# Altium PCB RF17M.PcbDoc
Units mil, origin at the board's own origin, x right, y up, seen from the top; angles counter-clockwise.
Board outline 1070 x 780 mil, 4 copper layers (Top Layer, MidLayer1, MidLayer2, Bottom Layer); 49 components, 57 nets, 260 pads, 101 vias.
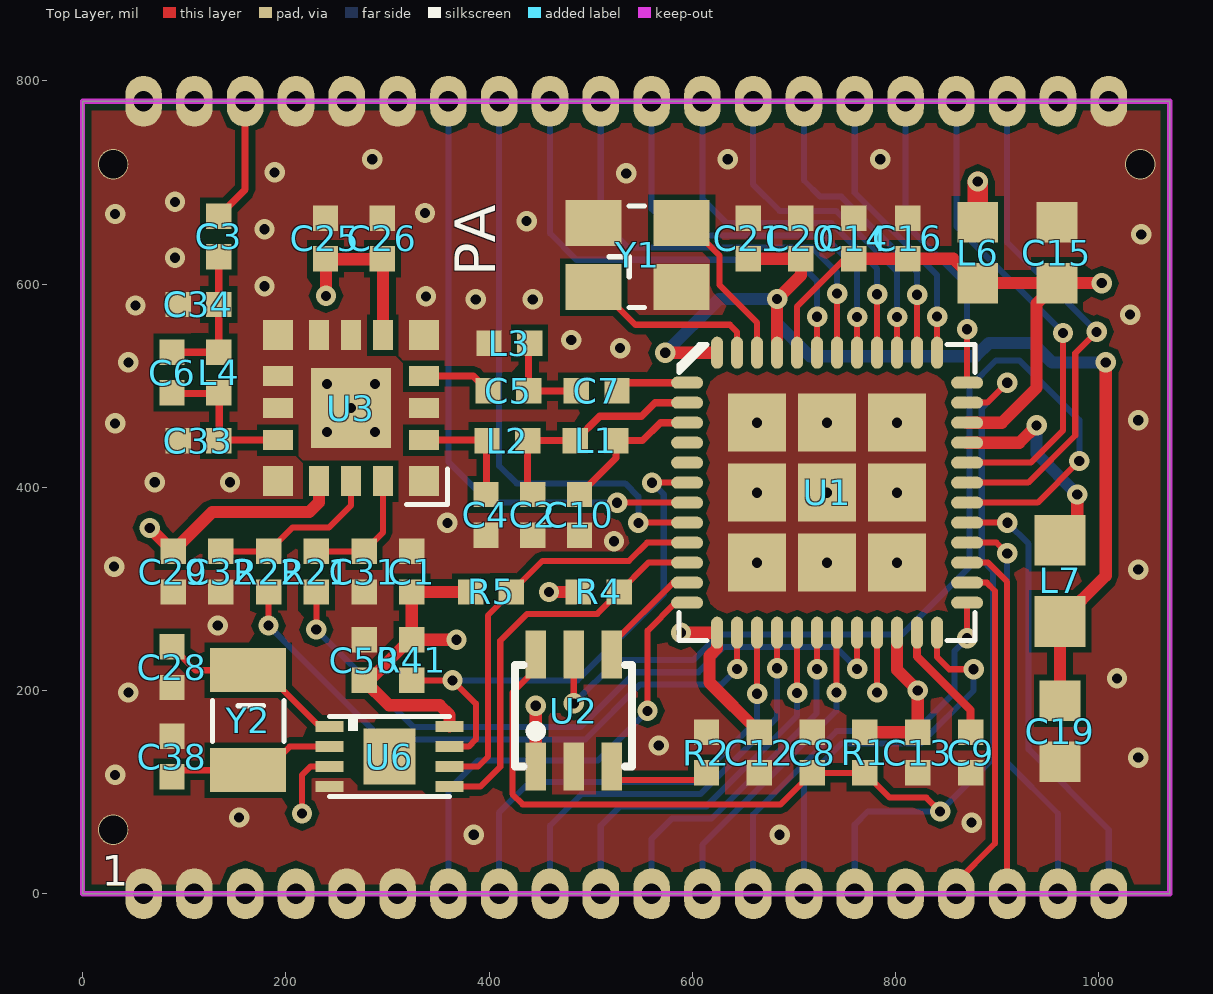
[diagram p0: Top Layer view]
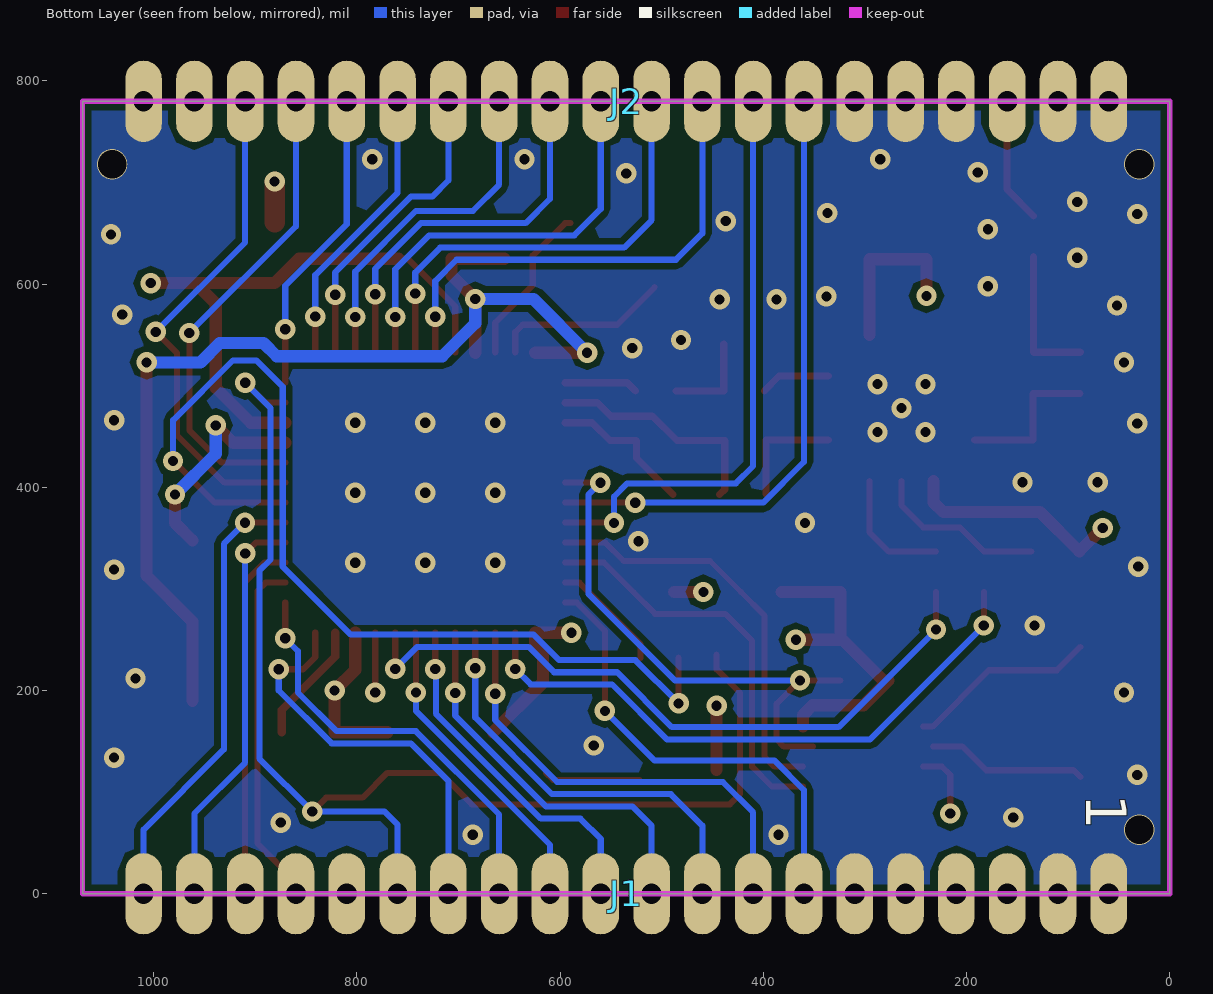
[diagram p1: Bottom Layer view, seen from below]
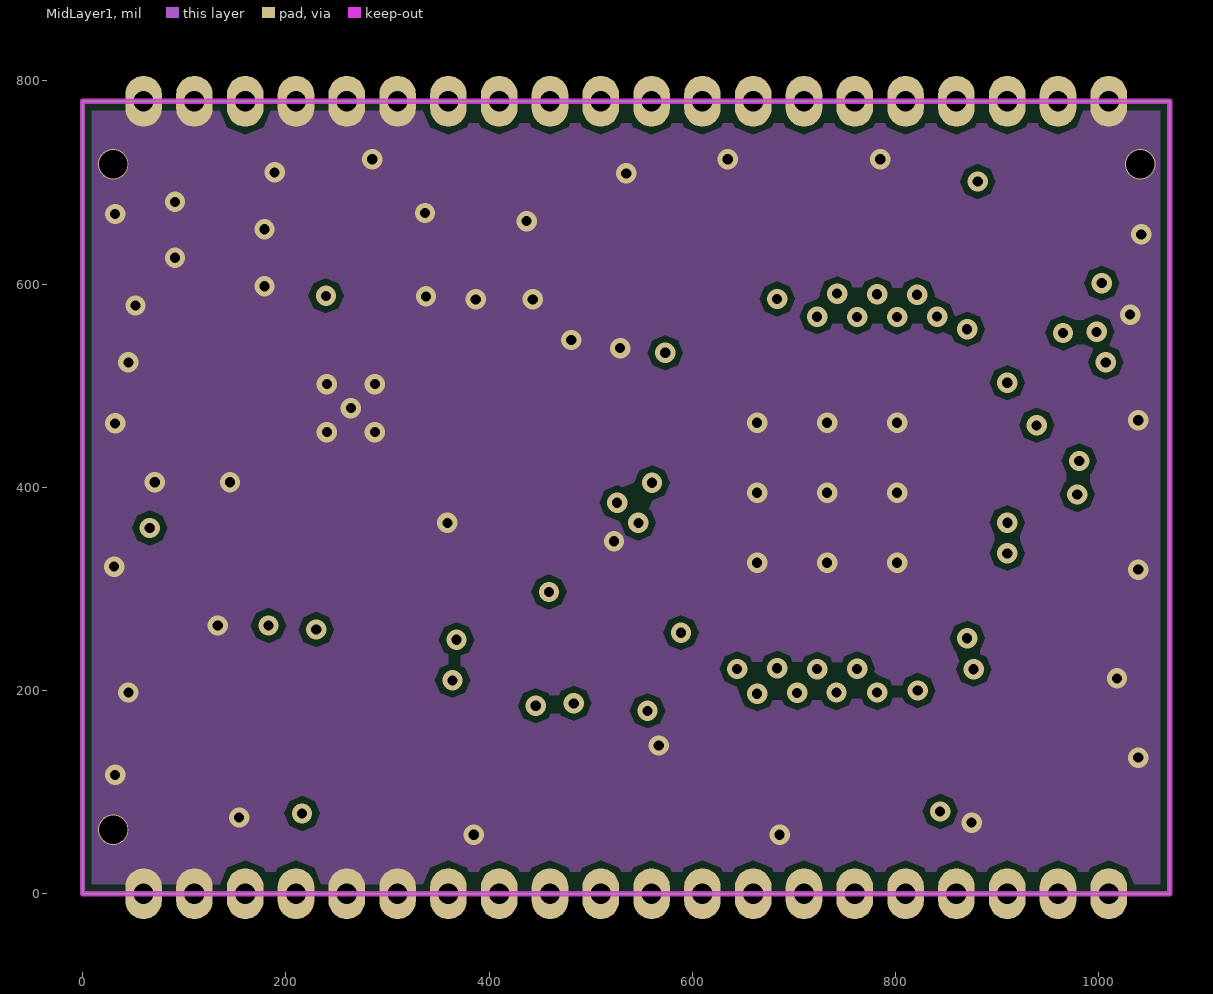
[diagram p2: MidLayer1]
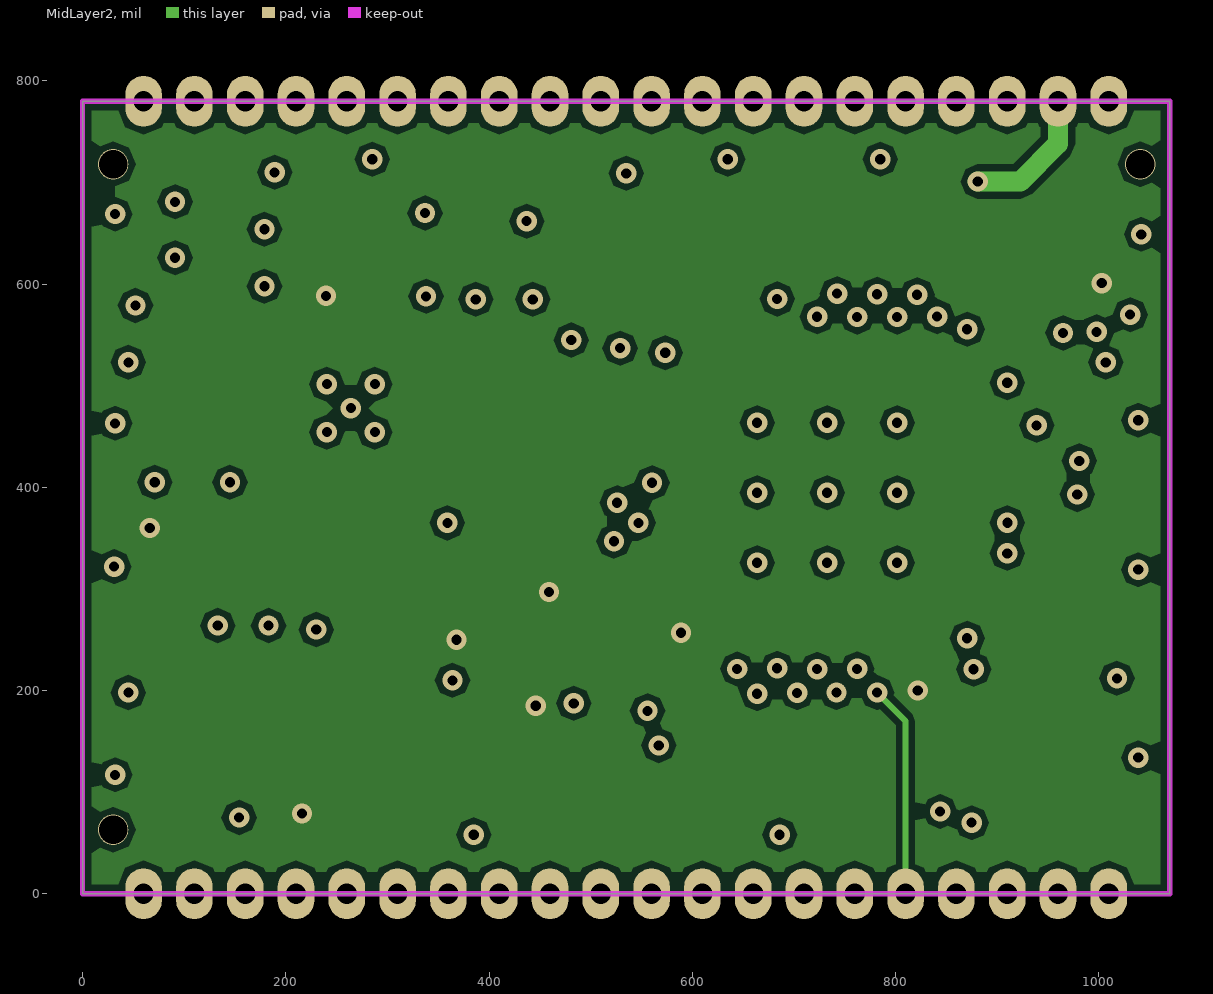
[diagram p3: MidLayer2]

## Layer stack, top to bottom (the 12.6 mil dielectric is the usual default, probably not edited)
Top Layer: signal copper 1.4
Dielectric: core 12.6, FR-4, Dk 4.8
MidLayer1: signal copper 1.4
Dielectric: prepreg 12.6, FR-4, Dk 4.8
MidLayer2: signal copper 1.4
Dielectric: core 12.6, FR-4, Dk 4.8
Bottom Layer: signal copper 1.4

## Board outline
0,0 1070,0 1070,780 0,780

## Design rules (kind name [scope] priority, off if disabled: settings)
Clearance [All] p1: gap=6
FabricationTestPointUsage TestPointUsage [All] p1: valid=0 allowmultiple=FALSE
FabricationTestpoint Testpoint [(IsPad And (OnTopLayer Or OnBottomLayer))] p1: side=3 testpointundercomponent=TRUE minsize=40 maxsize=100 preferedsize=60 minholesize=0 maxholesize=40 preferedholesize=32 testpointgrid=1 allowsidetop=TRUE allowsidebottom=TRUE usegrid=TRUE gridtolerance=0.01
PlaneConnect [All] p1: planeconnectstyle=Direct reliefexpansion=20 reliefentries=4 reliefconductorwidth=10 reliefairgap=10
PolygonConnect [All] p1: connectstyle=Direct reliefconductorwidth=16 reliefentries=4 polygonreliefangle="90 Angle"
RoutingVias [All] p1: holewidth=12 width=24 viastyle="Through Hole" minholewidth=10 minwidth=20 maxholewidth=50 maxwidth=100
SilkscreenOverComponentPads [All] p1: minsilkscreentomaskgap=10
SolderMaskExpansion [All] p1: expansion=4
Width [All] p1: maxlimit=100 minlimit=6 preferedwidth=8
24 further rules are at their usual default settings.

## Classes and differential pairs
pad class "New Class": U1-49 U2-33

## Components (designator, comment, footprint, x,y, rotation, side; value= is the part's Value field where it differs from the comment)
C1 "0.1uF" 0402 324,297 r90 top
C2 "GRM1555C1H3R6CA01D" 0402 443,353 r90 top
C3 "GRM1555C1H330JA01D" 0402 134,667 r270 top
C4 "GRM1555C1H2R2CA01D" 0402 397,353 r90 top
C5 "GRM1555C1H4R7CA01D" 0402 439,495 r180 top
C6 "GRM1555C1H2R2CA01D" 0402 88,493 r90 top
C7 "GRM1555C1H3R6CA01D" 0402 486,495 r0 top
C8 "0.1uF" 0402 718,119 r90 top
C9 "GRM188R70J105KA01D" 0402 874,119 r90 top
C10 "GRM1555C1H101JA01D" 0402 489,353 r90 top
C12 "GRM155R70J104KA01D" 0402 666,159 r270 top
C13 "GRM155R70J104KA01D" 0402 822,159 r270 top
C14 "GRM155R70J104KA01D" 0402 759,625 r90 top
C15 "GRM21BR70J106KE76L" 0603 959,601 r90 top
C16 "GRM155R70J104KA01D" 0402 812,625 r90 top
C19 "GRM21BR70J106KE76L" 0603 962,190 r270 top
C20 "GRM155R70J104KA01D" 0402 707,625 r90 top
C21 "GRM155R70J104KA01D" 0402 655,625 r90 top
C25 "GRM1555C1H2R2CA01D" 0402 239,665 r270 top
C26 "GRM1555C1H2R2CA01D" 0402 295,665 r270 top
C28 "6pF" 0402 88,203 r90 top
C29 "GRM1555C1H2R2CA01D" 0402 89,337 r270 top
C31 "GRM1555C1H2R2CA01D" 0402 277,337 r270 top
C32 "GRM1555C1H2R2CA01D" 0402 136,337 r270 top
C33 "GRM1555C1H2R2CA01D" 0402 94,446 r0 top
C34 "GRM1555C1H2R2CA01D" 0402 134,580 r180 top
C38 "6pF" 0402 88,155 r270 top
C50 "0.1uF" 0402 277,210 r90 top
J1 "CON20" SMD20_1.27MM 60,0 r0 top
J2 "CON20" SMD20_1.27MM 1010,780 r180 top
L1 "LQW15AN18NJ00D" 0402 525,446 r180 top
L2 "LQW15AN8N2G00D" 0402 438,446 r180 top
L3 "LQW15AN8N2G00D" 0402 400,542 r0 top
L4 "LQW15AN6N8G00D" 0402 134,493 r90 top
L6 "MPZ1608S471A" 0603 881,601 r90 top
L7 "MLZ2012N6R8L" 0805 962,348 r270 top
R1 "100K" 0402 770,119 r90 top
R2 "15K" 0402 614,159 r270 top
R4 "4.7K" 0402 488,297 r0 top
R5 "4.7K" 0402 382,297 r0 top
R21 "1K" 0402 230,297 r90 top
R22 "1K" 0402 183,297 r90 top
R41 "4.7K" 0402 324,250 r270 top
U1 "CC1310F128RGZR" RGZ0048 595,503 r0 top
U2 "TPL5010QDDCRQ1" SOT23-6L 446,125 r90 top
U3 "SKY66115-11" SKY66115-11 264,478 r180 top
U6 "MCP79410T-I/MNY" TDFN-8 302,135 r270 top
Y1 "TSX-3225 24.0000MF15X-AC3" TSX-3225 503,597 r0 top
Y2 "ABS07-32.768KHZ-T" ABS07 163,220 r270 top

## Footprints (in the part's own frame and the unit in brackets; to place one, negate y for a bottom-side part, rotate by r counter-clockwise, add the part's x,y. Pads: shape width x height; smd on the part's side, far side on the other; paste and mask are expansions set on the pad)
0402 [mil]
  rect 25x25 smd: 1(0,0) 2(40,0)
0603 [mil]
  rect 40x40 smd: 1(0,0) 2(60,0)
0805 [mil]
  rect 50x50 smd: 1(0,0) 2(80,0)
ABS07 [mm]
  rect 1.1x1.9 smd: 1(0,0) 2(2.5,0)
  silkscreen extent 0.76,-0.89 1.78,0.89
RGZ0048 [mm]
  oval 0.8x0.3 smd: 1(0,0) 2(0,-0.5) 3(0,-1) 4(0,-1.5) 5(0,-2) 6(0,-2.5) 7(0,-3) 8(0,-3.5) 9(0,-4) 10(0,-4.5) 11(0,-5) 12(0,-5.5) 25(7,-5.5) 26(7,-5) 27(7,-4.5) 28(7,-4) 29(7,-3.5) 30(7,-3) 31(7,-2.5) 32(7,-2) 33(7,-1.5) 34(7,-1) 35(7,-0.5) 36(7,0)
  oval 0.3x0.8 smd: 13(0.75,-6.25) 14(1.25,-6.25) 15(1.75,-6.25) 16(2.25,-6.25) 17(2.75,-6.25) 18(3.25,-6.25) 19(3.75,-6.25) 20(4.25,-6.25) 21(4.75,-6.25) 22(5.25,-6.25) 23(5.75,-6.25) 24(6.25,-6.25) 37(6.25,0.75) 38(5.75,0.75) 39(5.25,0.75) 40(4.75,0.75) 41(4.25,0.75) 42(3.75,0.75) 43(3.25,0.75) 44(2.75,0.75) 45(2.25,0.75) 46(1.75,0.75) 47(1.25,0.75) 48(0.75,0.75)
  rect 1.45x1.45 smd: 49(1.75,-1) 49(1.75,-4.5) 49(1.75,-2.75) 49(3.5,-4.5) 49(3.5,-2.75) 49(3.5,-1) 49(5.25,-4.5) 49(5.25,-2.75) 49(5.25,-1)
  silkscreen extent -0.2,-6.45 7.2,0.95
SKY66115-11 [mm]
  rect 0.75x0.75 smd: 1(-1.825,1.825) 5(-1.825,-1.825) 9(1.825,-1.825) 13(1.825,1.825)
  rect 0.75x0.5 smd: 2(-1.825,0.8) 3(-1.825,0) 4(-1.825,-0.8) 10(1.825,-0.8) 11(1.825,0) 12(1.825,0.8)
  rect 0.5x0.75 smd: 6(-0.8,-1.825) 7(0,-1.825) 8(0.8,-1.825) 14(0.8,1.825) 15(0,1.825) 16(-0.8,1.825)
  rect 2x2 smd: 17(0,0)
  silkscreen extent -2.41,1.52 -1.4,2.41
SMD20_1.27MM [mil]
  oval 36x80 smd far side: 1(0,0) 2(50,0) 3(100,0) 4(150,0) 5(200,0) 6(250,0) 7(300,0) 8(350,0) 9(400,0) 10(450,0) 11(500,0) 12(550,0) 13(600,0) 14(650,0) 15(700,0) 16(750,0) 17(800,0) 18(850,0) 19(900,0) 20(950,0)
  oval 36x50 hole 20: 1(0,0) 2(50,0) 3(100,0) 4(150,0) 5(200,0) 6(250,0) 7(300,0) 8(350,0) 9(400,0) 10(450,0) 11(500,0) 12(550,0) 13(600,0) 14(650,0) 15(700,0) 16(750,0) 17(800,0) 18(850,0) 19(900,0) 20(950,0)
SOT23-6L [mm] "IC"
  rect 1.2x0.508 smd: 1(0,0) 2(0,-0.95) 3(0,-1.9) 4(2.8,-1.9) 5(2.8,-0.95) 6(2.8,0)
  silkscreen extent 0,-2.41 2.54,0.51
TDFN-8 [mm]
  rect 1.4x1.3 smd: 0(0,0)
  rect 0.28x0.7 smd: 1(-0.75,-1.5) 2(-0.25,-1.5) 3(0.25,-1.5) 4(0.75,-1.5) 5(0.75,1.5) 6(0.25,1.5) 7(-0.25,1.5) 8(-0.75,1.5)
  silkscreen extent -1,-1.5 1,1.5
TSX-3225 [mm]
  rect 1.4x1.15 smd: 1(0,0) 2(2.2,0) 3(2.2,1.6) 4(0,1.6)
  silkscreen extent 0.38,-0.51 1.27,2.03

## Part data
C1 C8: library part CAP, "Capacitor"
C2 C7: "CAP, CERM, 3.6 pF, 50 V, +/- 5%, C0G/NP0, 0402"
C3: "CAP, CERM, 33 pF, 50 V, +/- 5%, C0G/NP0, 0402"
C4 C6 C25 C26 C29 C31 C32 C33 C34: "CAP, CERM, 2.2 pF, 50 V, +/- 5%, C0G/NP0, 0402"
C5: "CAP, CERM, 4.7 pF, 50 V, +/- 5%, C0G/NP0, 0402"
C9: "CAP, CERM, 1 µF, 6.3 V, +/- 10%, X7R, 0603"
C10: "CAP, CERM, 100 pF, 50 V, +/- 5%, C0G/NP0, 0402"
C12 C13 C14 C16 C20 C21: "CAP, CERM, 0.1 µF, 6.3 V, +/- 10%, X7R, 0402"
C15 C19: "CAP, CERM, 10 µF, 6.3 V, +/- 10%, X7R, 0805"
C28 C38: library part 06035A120JAT2A, "CAP, CERM, 12 pF, 50 V, +/- 5%, C0G/NP0, 0603"
C50: library part GRM155R70J104KA01D, "CAP, CERM, 0.1 µF, 6.3 V, +/- 10%, X7R, 0402"
J1 J2: "Connector"
L1: library part LQW15AN8N2G00D, "Inductor, Wirewound, 8.2 nH, 0.54 A, 0.14 ohm, SMD"
L2 L3: "Inductor, Wirewound, 8.2 nH, 0.54 A, 0.14 ohm, SMD"
L4: "Inductor, Wirewound, 6.8 nH, 0.7 A, 0.09 ohm, SMD"
L6: library part BLM18HE152SN1D, "Ferrite Bead, 1500 ohm @ 100 MHz, 0.5 A, 0603_950"
L7: library part CKS2125100M-T, "Inductor, Multilayer, Ferrite, 10 µH, 0.11 A, 0.52 ohm, SMD"
R1 R4 R5 R21 R22 R41: library part RES2
R2: library part Res2, "Resistor"
U1: "Sub-1 GHz and 2.4 GHz Multi-standard RF IC Family, RGZ0048A"
Y1: library part "TSX-3225 24.0000MF20G-AC3", "Crystal, 24 MHz, 9 pF, SMD"
Y2: library part "FC-12M 32.7680KA-A3", "Crystal, 32.768kHz, 12.5pF, SMD"

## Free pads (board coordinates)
  round 30 hole 28: 0(30,63) 0(30,718) 0(1041,718)

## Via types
v1: diameter 20, hole 10, Top Layer to Bottom Layer, tented both sides, 101 vias

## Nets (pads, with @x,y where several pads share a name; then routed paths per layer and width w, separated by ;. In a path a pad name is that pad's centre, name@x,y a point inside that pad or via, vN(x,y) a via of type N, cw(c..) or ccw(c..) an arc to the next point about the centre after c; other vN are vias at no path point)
CSD: R22.1 U1.14 | length 605
  Top Layer w6: v1(183,264) R22.1 ; v1(644.21,221.21) U1.14
  Bottom Layer w6: v1(183,264) 295,152 494.97,152 548.97,206 629,206 v1(644.21,221.21)
CTX: R21.1 U1.20 | length 686.4
  Top Layer w6: v1(230,260) R21.1 ; v1(762.32,221.32) U1.20
  Bottom Layer w6: v1(230,260) 326,164 490,164 544,218 606,218 631,243 740.65,243 v1(762.32,221.32)
DCDC_SW: L7.1 U1.33 | length 210.1
  Top Layer w12: U1.33 921.95,443.95 v1(939,461) ; L7.1 979,365 v1@979,391
  Bottom Layer w12: v1(939,461) 939,433 v1(979,393)
DONE: U1.11 U2.4 | length 112.8
  Top Layer w6: U2.4@520.8,232.24 520.8,245.8 581.15,306.15 U1.11
DVCC: J2.2 L6.2 | length 157.8
  Top Layer w20: L6.2 v1(881,701)
  MidLayer2 w20: v1(881,701) 923,701 960,738 J2.2@960,761.5
GND: C1.2 C2.1 C4.1 C8.2 C9.1 C10.1 C12.2 C13.2 C14.2 C15.2 C16.2 C19.2 C20.2 C21.2 C25.1 C26.1 C28.1 C29.2 C31.2 C32.2 C33.1 C34.2 C38.1 C50.2 J1.1 J1.2 J1.5 J1.6 J2.1 J2.15 J2.16 J2.17 J2.19 J2.20 L3.1 pad.0 R2.1 U1.49 U2.2 U3.1 U3.3 U3.5 U3.7 U3.8 U3.9 U3.10 U3.11 U3.13 U3.17 U6.4 Y1.2 Y1.4
  other v1: 385,58 686,58 875,70 154,75 32,117 1039,134 567,146 45,198 1018,212 133,264 1039,319 31,322 663.9,325.84 732.8,325.84 801.69,325.84 523,347 359,365 663.9,394.73 732.8,394.73 801.69,394.73 71,405 145,405 240.38,454.38 287.62,454.38 32,463 663.9,463.63 732.8,463.63 801.69,463.63 1039,466 264,478 240.38,501.62 287.62,501.62 45,523 529,537 481,545 1031,570 52,579 387,585 443,585 338,588 179,598 91,626 1042,649 179,654 437,662 32,669 337,670 91,681 535,709 189,710 285,723 635,723 785,723
I2C_SCL: R5.2 U1.9 U6.6 | length 406.6
  Top Layer w6: U6.6 389.16,125.16 399,135 399,274 R5.2 452.52,327.52 537.52,327.52 555.52,345.52 U1.9
I2C_SDA: R4.2 U1.10 U6.5 | length 397.9
  Top Layer w6: U6.5 391.47,105.47 411,125 411,249 437.5,275.5 506.5,275.5 R4.2 556.84,325.84 U1.10
IO0: J1.11 U1.18 | length 335.8
  Top Layer w6: v1(722.95,221.05) U1.18
  Bottom Layer w6: J1.11@560,11.5 560,54 580,74 618.97,74 722.27,177.3 722.27,220.36 v1(722.95,221.05)
IO1: J1.12 U1.19 | length 302.4
  Top Layer w6: v1(742,198) 742,256.3 U1.19
  MidLayer1 w6: v1@742,196 v1(742,198)
  Bottom Layer w6: J1.12@610,11.5 610,48.06 742,180.06 v1(742,198)
IO2/AD0: J2.8 U1.39 | length 327.5
  Top Layer w6: U1.39 v1(801.69,567.69)
  Bottom Layer w6: J2.8@660,768.5 660,698 686,672 741.97,672 801.66,612.31 v1(801.69,567.69)
IO3/AD1: J2.7 U1.38 | length 294.4
  Top Layer w6: U1.38 v1(821.38,589.62)
  Bottom Layer w6: J2.7@710,768.5 710,702 725.86,686.14 746.86,686.14 821.38,611.62 v1(821.38,589.62)
IO4/AD2: J2.6 U1.37 | length 269.5
  Top Layer w6: U1.37 v1(841.06,568.06)
  Bottom Layer w6: J2.6@760,768.5 760,689.97 841.06,608.91 v1(841.06,568.06)
IO5/AD3: J2.5 U1.36 | length 290.6
  Top Layer w6: U1.36 v1(870.59,555.59)
  Bottom Layer w6: J2.5@810,768.5 810,659 870.59,598.41 v1(870.59,555.59)
IO6: J2.4 U1.32 | length 463.5
  Top Layer w6: U1.32 933.26,424.26 965,456 v1(965,552)
  Bottom Layer w6: J2.4@860,768.5 860,657 v1(965,552)
IO7: J2.3 U1.31 | length 488.3
  Top Layer w6: U1.31 930.55,404.58 977,451.03 977,532 v1(998,553)
  Bottom Layer w6: J2.3@910,768.5 910,641 v1(998,553)
IO8/IRQ0: J1.20 U1.29 | length 434.7
  Top Layer w6: U1.29 v1(910.21,365.21)
  Bottom Layer w6: v1(910.21,365.21) 931,344.41 931,142 1010,63 J1.20@1010,11.5
IO9/IRQ1: J1.19 U1.28 | length 388
  Top Layer w6: U1.28 899.48,345.52 v1(910,335)
  Bottom Layer w6: v1(910,335) 910,129 960,79 J1.19@960,11.5
IO10/IRQ2: J1.18 U1.27 | length 342.7
  Top Layer w6: U1.27 891.16,325.84 910,307 J1.18@910,11.5
IO11/IRQ3: J1.17 U1.26 | length 333
  Top Layer w6: J1.17@860,11.5 898,49.5 898,298 889.85,306.15 U1.26
IO12/IRQ4: J1.16 U1.21 | length 257
  Top Layer w6: v1(782.01,197.99) U1.21
  MidLayer2 w6: v1(782.01,197.99) 810,170 J1.16@810,11.5
IO14: J1.10 U1.17 | length 375.3
  Top Layer w6: v1(703.27,197.73) U1.17
  Bottom Layer w6: J1.10@510,11.5 510,67 529,86 614,86 703.27,175.27 v1(703.27,197.73)
IO15: J1.9 U1.16 | length 406.6
  Top Layer w6: v1(683.58,222) U1.16
  Bottom Layer w6: J1.9@460,11.5 460,67 491,98 608,98 683.58,173.58 v1(683.58,222)
IO16: J1.8 U1.15 | length 446.1
  Top Layer w6: v1(663.9,196.9) U1.15
  Bottom Layer w6: J1.8@410,11.5 410,80 440,110 603.03,110 663.9,170.87 v1(663.9,196.9)
IO17: J1.7 U1.12 | length 448.2
  Top Layer w6: v1(556,180) 556,259 583.47,286.47 U1.12
  Bottom Layer w6: J1.7@360,11.5 360,102 389,131 507,131 v1(556,180)
JTCK: J1.13 U1.25 | length 407.9
  Top Layer w6: v1(870.59,251.41) U1.25
  Bottom Layer w6: J1.13@660,11.5 660,78 742,160 820,160 858,198 858,238.82 v1(870.59,251.41)
JTMS: J1.14 U1.24 | length 389.2
  Top Layer w6: U1.24 841.06,232.94 853,221 v1(877,221)
  Bottom Layer w6: J1.14@710,11.5 710,111.03 746.97,148 824.97,148 877,200.03 v1(877,221)
MCU_RST: C8.1 J1.15 R1.1 U1.35 U2.6 | length 1252.4
  Top Layer w6: U2.6 446,221 423,198 423,98 433,88 687,88 C8.1 R1.1 794.38,94.62 830.38,94.62 v1(844,81) ; U1.35 890.32,483.32 v1(910,503)
  Bottom Layer w6: J1.15@760,11.5 760,68 773,81 v1(844,81) 896,133 896,318 885,329 885,478 v1(910,503)
MCU_RXD: J2.14 U1.7 | length 595.1
  Top Layer w6: v1(526.11,384.89) U1.7
  Bottom Layer w6: J2.14@360,768.5 360,425 400.11,384.89 v1(526.11,384.89)
MCU_TXD: J2.13 U1.8 | length 570.6
  Top Layer w6: v1@547.21,365.21 U1.8
  Bottom Layer w6: J2.13@410,768.5 410,421 427.11,403.89 533.98,403.89 547,390.87 v1(547,365)
MFP: R41.2 U1.6 U6.7 | length 545.4
  Top Layer w6: R41.2 v1(364,210) 387,187 387,152 379.84,144.84 U6.7 ; U6.7@351.06,144.84 U6.7 ; U6.7@367.84,144.84 U6.7 ; v1(560.42,404.58) U1.6
  Bottom Layer w6: v1(364,210) 487,210 572,295 572,393 v1(560.42,404.58)
NetC2_2: C2.2 L1.2 L2.1 U1.2 | length 227.5
  Top Layer w7: C2.2 438,398 L2.1 L1.2 509,470 550,470 563.32,483.32 U1.2
NetC3_2: C3.2 C6.2 C34.1 L4.2 | length 140
  Top Layer w7: C6.2 L4.2 C34.1 C3.2
NetC4_2: C4.2 L2.2 U3.2 | length 114.7
  Top Layer w7: U3.2 397.5,446.5 C4.2@397.5,393.5
NetC5_1: C5.1 C7.1 L3.2 | length 93
  Top Layer w7: L3.2@439,541 C5.1 C7.1
NetC5_2: C5.2 U3.4 | length 69.2
  Top Layer w7: U3.4 384.5,509.5 C5.2
NetC6_1: C6.1 C33.2 L4.1 U3.12 | length 149.6
  Top Layer w7: C6.1@88.5,492.5 134.5,492.5 134.5,446.5 U3.12
NetC7_2: C7.2 U1.1 | length 72.3
  Top Layer w7: C7.2 534,503 U1.1
NetC9_2: C9.2 U1.23 | length 119.7
  Top Layer w8: U1.23 821.38,233.62 874,181 C9.2
NetC10_2: C10.2 L1.1 U1.3 | length 145.2
  Top Layer w7: C10.2 525,429 L1.1 551,446 568.63,463.63 U1.3
NetC28_2: C28.2 U6.1 Y2.1 | length 187.4
  Top Layer w6: C28.2 111,220 Y2.1 178,220 233.47,164.53 U6.1
NetC31_1: C31.1 R21.2 U3.16 | length 123.8
  Top Layer w6: R21.2 C31.1 295.5,355.5 U3.16
NetC32_1: C32.1 R22.2 U3.15 | length 170.8
  Top Layer w6: C32.1 R22.2 206.61,360.61 242.61,360.61 264,382 U3.15
NetC38_2: C38.2 U6.2 Y2.2 | length 157.3
  Top Layer w6: C38.2 94.57,121.57 Y2.2 180.57,121.57 203.84,144.84 U6.2@232.94,144.84
NetR2_2: R2.2 U2.3 | length 94.9
  Top Layer w6: U2.3@522,112 607,112 R2.2
ON/SLEEP: J2.10 U1.41 | length 403.5
  Top Layer w6: U1.41 v1(762.32,567.68)
  Bottom Layer w6: J2.10@560,768.5 560,674 586,648 729,648 762.32,614.68 v1(762.32,567.68)
RF_ANT: C3.1 J2.18 | length 107.8
  Top Layer w7: C3.1 160,693 J2.18@160,764
RX_LED: J2.11 U1.42 | length 438.4
  Top Layer w6: U1.42 v1(742.64,590.64)
  Bottom Layer w6: J2.11@510,768.5 510,663 537,636 718,636 742.64,611.36 v1(742.64,590.64)
TX/RX: J2.9 U1.40 | length 367.6
  Top Layer w6: U1.40 v1(782.01,590.01)
  Bottom Layer w6: J2.9@610,768.5 610,684 634,660 737,660 782.01,614.99 v1(782.01,590.01)
TX_LED: J2.12 U1.43 | length 471.4
  Top Layer w6: U1.43 v1(722.95,567.95)
  Bottom Layer w6: J2.12@460,768.5 460,650 486,624 702,624 722.95,603.05 v1(722.95,567.95)
VDD_RF1: J1.3
VDD_RF2: J1.4
VDDR: C19.1 C20.1 C21.1 L7.2 U1.45 U1.48 | length 1063
  Top Layer w12: v1(573.47,532.53) U1.48 ; C21.1 C20.1 707,608.83 v1(683.58,585.42) U1.45 ; C19.1 L7.2 1007,313 v1(1007,523)
  Bottom Layer w12: v1(573.47,532.53) 626.36,585.42 v1(683.58,585.42) 683.58,561.42 716,529 879,529 892,542 935,542 954,523 v1(1007,523)
VDDS: C1.1 C12.1 C13.1 C14.1 C15.1 C16.1 C25.2 C26.2 C29.1 C50.1 L6.1 R1.2 R4.1 R5.1 R41.1 U1.13 U1.22 U1.34 U1.44 U2.1 U3.6 U3.14 U6.3 U6.8 | length 1745
  Top Layer w6: v1(216,79) 216,117 224.16,125.16 U6.3 ; U1.44 703.27,578.14 750.13,625 C14.1
  Top Layer w12: v1(66,360) C29.1 127.61,375.61 223,375.61 232.5,385.11 U3.14 ; v1(239.5,588.5) 239.5,624.5 295.5,624.5 U3.6 ; C50.1 301.5,185.5 351.5,185.5 361.06,175.94 U6.8 ; C50.1@282.03,210 322.03,250 R41.1 ; v1(368,250) R41.1 ; R5.1 C1.1 R41.1 ; U2.1@446,122 v1(446,185) ; v1(459,297) R4.1 ; v1(588.94,256.94) U1.13 624.53,241.53 617,234 617,208 C12.1 ; C14.1 C16.1 857,625 L6.1 C15.1 ; R1.2 C13.1 v1(822,200) 801.69,220.31 U1.22 ; U1.34 904.63,463.63 939,498 939,581 C15.1 ; v1(1003,601) C15.1
WAKE: U1.30 U2.5 | length 982.2
  Top Layer w6: v1(483.4,187.4) U2.5@483.4,232.24 ; U1.30 939.89,384.89 v1(981,426) v1@981,423
  Bottom Layer w6: v1(483.4,187.4) 526,230 601.03,230 626.03,255 806,255 873,322 873,499 899,525 922,525 981,466 v1(981,426) v1@982,427
X24M_N: U1.46 Y1.3 | length 161.4
  Top Layer w6: Y1.3 595.01,659.99 627,628 627,599 663.9,562.1 U1.46
X24M_P: U1.47 Y1.1 | length 175.8
  Top Layer w6: Y1.1@507,597 544,560 637,560 644.21,552.79 U1.47
pads on no net: U1.4 U1.5 U6.0

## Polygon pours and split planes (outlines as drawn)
GND on Top Layer "Bottom Layer-No Net" (solid, remove dead copper, pour order 2): 0,0 1070,0 1070,780 0,780 0,0
GND on MidLayer1 "Bottom Layer-No Net" (solid, remove dead copper, pour order 4): 0,0 1070,0 1070,780 0,780 0,0
VDDS on MidLayer2 "Bottom Layer-No Net" (solid, remove dead copper, pour order 6): 0,0 1070,0 1070,780 0,780 0,0
GND on Bottom Layer "Bottom Layer-No Net" (solid, remove dead copper, pour order 8): 0,0 1070,0 1070,780 0,780 0,0

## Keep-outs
Keep-Out Layer:
  lines w5: 0,0 0,780 10,780 1060,780 1070,780 1070,0 1060,0 10,0 0,0

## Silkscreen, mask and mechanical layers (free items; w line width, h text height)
Top Overlay:
  lines w5: 587.13,512.84 614.69,540.4 ; 587.13,517.84 609.69,540.4
  text "PA" at 406,608 h40 r90
  text "1" at 19,8 h30
Bottom Overlay:
  text "1" at 82,98 h40 r90
Top Solder:
  rectangle: 250.08,708 475.95,740
  rectangle: 594.06,708 819.92,740
  region: 6.63,740 6.63,708 131.97,708 131.97,740
  region: 131.97,41 131.97,73 6.63,73 6.63,41
  region: 1063.37,41 1063.37,73 938.03,73 938.03,41
  rectangle: 594.06,41 819.92,73
  rectangle: 250.08,41 475.94,73
  region: 1063.37,740 1024,740 1024,622.03 1063.37,622.03
  region: 1063.37,503.92 1024,503.92 1024,277.08 1063.37,277.08
  rectangle: 6.63,277.08 46,503.92
  rectangle: 6.63,41 46,158.97
  rectangle: 6.63,622.03 46,740
  rectangle: 1024,41 1063.37,158.97
  region: 938.03,740 938.03,708 1063.37,708 1063.37,740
